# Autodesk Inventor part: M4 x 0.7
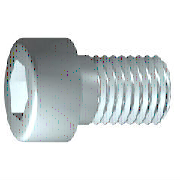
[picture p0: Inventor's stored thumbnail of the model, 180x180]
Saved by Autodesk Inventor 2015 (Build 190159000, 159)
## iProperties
IsCustomPart: 0
Created: 2015-10
Part Number: M4 x 0.7
Material: 강철, 연강
Description: 6각머리 태핑 나사
Document SubType Name: Modeling
Standard: KS B 1003
Designer: mdu
Standards Organization: KS
Language: ko-KR
Size Designation: M 4 x 25
Categories: <MemberInstance><Categories><Category DisplayName="조임쇠" InternalName="e4da775c-781d-43d5-af7c-5136215cf5a6" Mnemonic="FSTN"><Category DisplayName="볼트" InternalN
Density: 7.86 g/cm^3
Mass: 3.51868 g
Surface Area: 4.94215 cm^2
Volume: 0.447669 cm^3
Appearance: 강철
Author: mdu
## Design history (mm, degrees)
sketch "스케치1"
  geometry: L1 (-1, 0)-(25, 0); L2 (25, 0)-(25, 2); L3 (25, 2)-(1.75, 2); L4 (1.75, 2)-(1.32, 2); L5 (1.32, 2)-(0, 2); L6 (0, 2)-(0, 3.5); L7 (0, 3.5)-(-4, 3.5); L8 (-4, 3.5)-(-4, 1.732); L9 (-4, 1.732)-(-2, 1.732); L10 (-2, 1.732)-(-1, 0); L11 (-9.8, 0)-(30.8, 0) reference; L12 (0, -0.7)-(0, 4.2) reference; L13 (1.75, 2)-(0, 2)
  constraints: 22 end point, 6 parallel, 2 collinear, 2 perpendicular, 1 horizontal, 1 point on line
  dimensions: "d1" = 23.25 distance from line of L3.end L2 (= GEL); "d2" = 0.42952 distance of L4.end L3.end (computed from GAL); "d3" = 4 distance between parallel lines of L8 L6 (= KOH); "d4" = 2 distance of L8.end L9.end (= INTI); "d5" = 60 deg angle of L10 L1; "d6" = 4 diameter of L3 L1 (= GD); "d7" = 4 diameter of L5 L1 (= BDM); "d8" = 3.4641 diameter of L9 L1 (= 1.1547 x SW); "d9" = 7 diameter of L7 L1 (= KOD); "d26" = 25 distance between parallel lines of L12 L2 (= NLG)
revolve "본체" sketch "스케치1" stored, may be unused: angle "d10" = 90 deg
sketch "스케치2"
  geometry: L1 (0, -4.9)-(0, 4.9) reference; L2 (-4.9, 0)-(4.9, 0) reference; L3 (1.732, 0)-(0.866, -1.5); L4 (0.866, -1.5)-(-0.866, -1.5); L5 (-0.866, -1.5)-(-1.732, 0); L6 (-1.732, 0)-(-0.866, 1.5); L7 (-0.866, 1.5)-(0.866, 1.5); L8 (0.866, 1.5)-(1.732, 0); 2 further points
  constraints: 12 end point, 1 coincident, 1 horizontal alignment, 1 point on line, 12 other
extrude "슬롯" join sketch "스케치2" stored distance "d11" = 10; taper "d12" = 0 deg
workplane "Work Plane1"
fillet "Fillet2" dims "d30" = 0.1 (= R)
body "Solid1"
fillet "모깎기1" dims "d17" = 0.4 (= RR)
feature "스레드" dims "d13" = 23.25 (= GEL), "d14" = 0
chamfer "모따기1" distance "d15" = 0.42941 (= -0.5 x SPD + 0.5 x GD); stored, may be unused: second distance "d16" = 0.42941 (= GUL), angle "d27" = 45 deg
other parameters: "GD" = 4 (= NND) [user parameter; used in 2 equation terms], "NLG" = 25 [user parameter; used in 1 equation term], "GEL" = 23.25 [user parameter; used in 2 equation terms], "KOD" = 7 [user parameter; used in 1 equation term], "KOH" = 4 [user parameter; used in 1 equation term], "INTI" = 2 [user parameter; used in 1 equation term], "GAL" = 0.42941 (= 0.61345 x PTC) [user parameter; used in 1 equation term], "GUL" = 0.42941 (= 0.61345 x PTC) [user parameter; used in 1 equation term], "BDM" = 4 (= NND) [user parameter; used in 1 equation term], "SW" = 3 [user parameter; used in 2 equation terms], "RR" = 0.4 [user parameter; used in 1 equation term], "SPD" = 3.14117 (= NND - 1.2269 x PTC) [user parameter; used in 1 equation term], "d19" = 0, "d28" = 0, "d29" = 0, "R" = 0.1 [user parameter; used in 1 equation term], "PHH" = 0.2 [user parameter], "GD1" = 3.14117 (= THREADDIA - 1.2269 x PTC) [user parameter], "THREADDIA" = 4 [user parameter; used in 1 equation term], "FAWI" = 45 deg [user parameter], "TPU" = 14.28571 (computed from PTC) [user parameter], "PTC" = 0.7 [user parameter; used in 5 equation terms], "NND" = 4 [user parameter; used in 3 equation terms], "TOA" = 30 deg [user parameter], "E0" = 3.465 (= 1.155 x SW) [user parameter]
